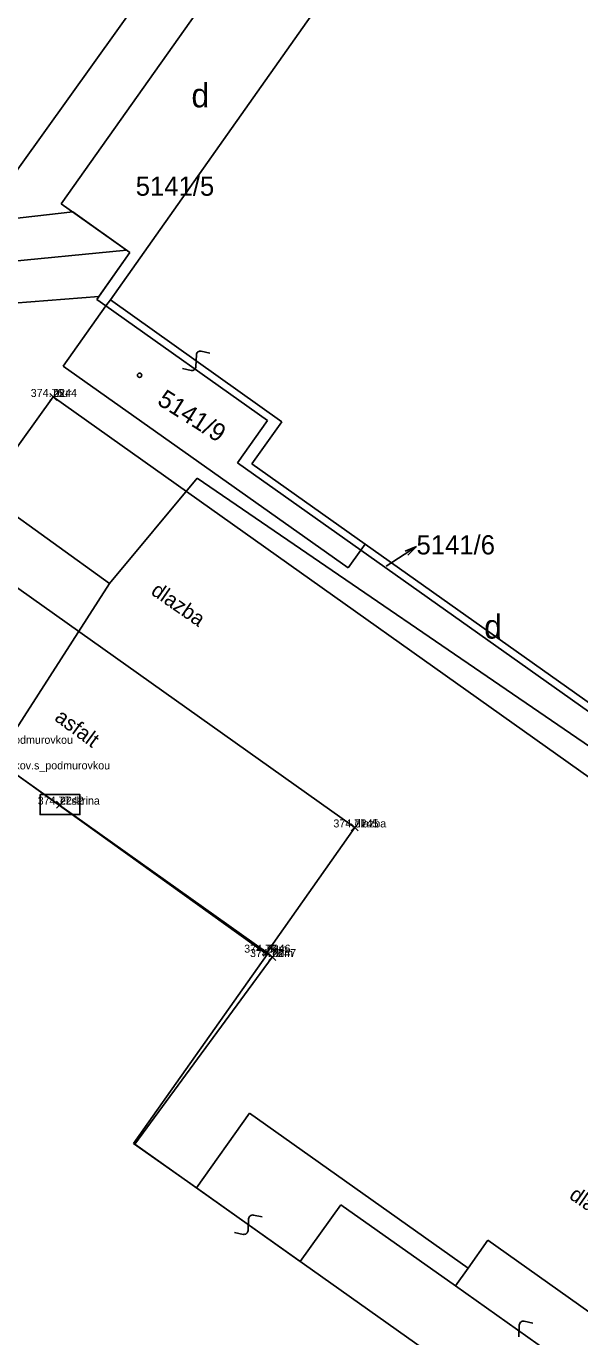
# Model space of a CAD drawing. Extents: x -400488 to -400124, y -1251493 to -1251223.
# Drawn here: x -400338.08 to -400324.23, y -1251319.82 to -1251287.06 of the extents above; entities that cross this region are included whole.
import ezdxf

# ---------------------------------------------------------------- set-up
doc = ezdxf.new("R2010")
doc.units = 0
for name, color, linetype in [('Level 20', 7, 'Continuous'), ('Level 21', 7, 'Continuous'), ('Level 22', 7, 'Continuous'), ('Level 23', 7, 'Continuous'), ('Level 31', 7, 'Continuous'), ('Level 32', 7, 'Continuous'), ('Level 34', 7, 'Continuous'), ('Level 35', 7, 'Continuous'), ('Level 53', 7, 'Continuous'), ('Level 63', 7, 'Continuous')]:
    doc.layers.add(name, color=color, linetype=linetype)

msp = doc.modelspace()

# ---------------------------------------------------------------- linework, layer by layer
at = {"layer": 'Level 20'}
for p, q in [((-400337.488, -1251296.418), (-400337.312, -1251296.242)), ((-400337.312, -1251296.418), (-400337.488, -1251296.242)), ((-400337.318, -1251306.608), (-400337.142, -1251306.432)), ((-400337.142, -1251306.608), (-400337.318, -1251306.432)), ((-400329.948, -1251307.178), (-400329.772, -1251307.002)), ((-400329.772, -1251307.178), (-400329.948, -1251307.002)), ((-400332.148, -1251310.308), (-400331.972, -1251310.132)), ((-400331.972, -1251310.308), (-400332.148, -1251310.132)), ((-400332.008, -1251310.418), (-400331.832, -1251310.242)), ((-400331.832, -1251310.418), (-400332.008, -1251310.242))]:
    msp.add_line(p, q, dxfattribs=at)
at = {"layer": 'Level 31'}
msp.add_lwpolyline([(-400341.165, -1251294.579), (-400341.04, -1251297.05), (-400340.98, -1251298.42), (-400339.65, -1251299.4), (-400340.05, -1251299.86), (-400329.86, -1251307.09), (-400332.06, -1251310.22)], dxfattribs=at)
at = {"layer": 'Level 34'}
for points in [[(-400343.58, -1251312.05), (-400339.12, -1251305.887), (-400338.95, -1251305.64), (-400338.78, -1251305.45), (-400332.06, -1251310.22), (-400331.92, -1251310.33)], [(-400318.045, -1251327.281), (-400335.362, -1251315.009), (-400331.92, -1251310.33)]]:
    msp.add_lwpolyline(points, dxfattribs=at)
at = {"layer": 'Level 35'}
msp.add_lwpolyline([(-400338.97, -1251298.5), (-400337.4, -1251296.33), (-400320.87, -1251308.06), (-400319.57, -1251311.74)], dxfattribs=at)
at = {"layer": 'Level 53'}
msp.add_lwpolyline([(-400337.73, -1251306.27), (-400336.73, -1251306.27), (-400336.73, -1251306.77), (-400337.73, -1251306.77)], close=True, dxfattribs=at)
at = {"layer": 'Level 63'}
for p, q in [((-400333.05, -1251283.33), (-400342.41, -1251296.38)), ((-400342.41, -1251296.38), (-400333.05, -1251283.33)), ((-400328.67, -1251283.57), (-400335.97, -1251293.9)), ((-400335.97, -1251293.9), (-400328.67, -1251283.57)), ((-400332.29, -1251284.57), (-400337.2, -1251291.5)), ((-400337.2, -1251291.5), (-400332.29, -1251284.57)), ((-400339.25, -1251291.97), (-400336.91, -1251291.7)), ((-400337.2, -1251291.5), (-400335.48, -1251292.72)), ((-400335.48, -1251292.72), (-400337.2, -1251291.5)), ((-400336.91, -1251291.7), (-400335.48, -1251292.72)), ((-400340.05, -1251293.1), (-400335.57, -1251292.66)), ((-400335.48, -1251292.72), (-400336.31, -1251293.89)), ((-400336.31, -1251293.89), (-400335.48, -1251292.72)), ((-400335.48, -1251292.72), (-400336.26, -1251293.82)), ((-400336.26, -1251293.82), (-400340.59, -1251294.16)), ((-400336.08, -1251294.05), (-400337.15, -1251295.56)), ((-400337.15, -1251295.56), (-400336.08, -1251294.05)), ((-400336.31, -1251293.89), (-400336.08, -1251294.05)), ((-400336.08, -1251294.05), (-400336.31, -1251293.89)), ((-400335.97, -1251293.9), (-400336.08, -1251294.05)), ((-400336.08, -1251294.05), (-400335.97, -1251293.9)), ((-400336.08, -1251294.05), (-400332.04, -1251296.92)), ((-400332.04, -1251296.92), (-400336.08, -1251294.05)), ((-400331.68, -1251296.95), (-400335.97, -1251293.9)), ((-400333.831, -1251295.572), (-400333.819, -1251295.278)), ((-400333.698, -1251295.184), (-400333.48, -1251295.232)), ((-400337.15, -1251295.56), (-400330.02, -1251300.6)), ((-400330.02, -1251300.6), (-400337.15, -1251295.56)), ((-400334.17, -1251295.618), (-400333.952, -1251295.666)), ((-400342.41, -1251296.38), (-400335.99, -1251300.99)), ((-400335.99, -1251300.99), (-400342.41, -1251296.38)), ((-400332.04, -1251296.92), (-400332.79, -1251297.98)), ((-400332.79, -1251297.98), (-400332.04, -1251296.92)), ((-400332.43, -1251298), (-400331.68, -1251296.95)), ((-400332.79, -1251297.98), (-400329.71, -1251300.16)), ((-400329.71, -1251300.16), (-400332.79, -1251297.98)), ((-400329.6, -1251300.01), (-400332.43, -1251298)), ((-400335.99, -1251300.99), (-400333.8, -1251298.36)), ((-400333.8, -1251298.36), (-400335.99, -1251300.99)), ((-400333.8, -1251298.36), (-400320.99, -1251307.12)), ((-400320.99, -1251307.12), (-400333.8, -1251298.36)), ((-400330.02, -1251300.6), (-400329.71, -1251300.16)), ((-400329.71, -1251300.16), (-400330.02, -1251300.6)), ((-400329.71, -1251300.16), (-400329.6, -1251300.01)), ((-400329.6, -1251300.01), (-400329.71, -1251300.16)), ((-400329.71, -1251300.16), (-400323.81, -1251304.33)), ((-400323.81, -1251304.33), (-400329.71, -1251300.16)), ((-400329.6, -1251300.01), (-400323.7, -1251304.18)), ((-400323.7, -1251304.18), (-400329.6, -1251300.01)), ((-400329.07, -1251300.56), (-400328.316, -1251300.069)), ((-400328.316, -1251300.069), (-400328.6, -1251300.182)), ((-400328.535, -1251300.283), (-400328.316, -1251300.069)), ((-400335.99, -1251300.99), (-400338.69, -1251305.2)), ((-400338.69, -1251305.2), (-400335.99, -1251300.99)), ((-400338.84, -1251305.4), (-400332.05, -1251310.27)), ((-400332.05, -1251310.27), (-400335.39, -1251314.99)), ((-400335.39, -1251314.99), (-400332.05, -1251310.27)), ((-400333.82, -1251316.1), (-400332.49, -1251314.23)), ((-400332.49, -1251314.23), (-400333.82, -1251316.1)), ((-400332.49, -1251314.23), (-400327.02, -1251318.11)), ((-400327.02, -1251318.11), (-400332.49, -1251314.23)), ((-400335.39, -1251314.99), (-400333.82, -1251316.1)), ((-400333.82, -1251316.1), (-400335.39, -1251314.99)), ((-400333.82, -1251316.1), (-400331.22, -1251317.94)), ((-400331.22, -1251317.94), (-400330.21, -1251316.52)), ((-400330.21, -1251316.52), (-400327.34, -1251318.55)), ((-400332.526, -1251317.167), (-400332.514, -1251316.873)), ((-400332.393, -1251316.779), (-400332.175, -1251316.827)), ((-400332.865, -1251317.213), (-400332.647, -1251317.261)), ((-400327.02, -1251318.11), (-400326.53, -1251317.41)), ((-400326.53, -1251317.41), (-400327.02, -1251318.11)), ((-400326.53, -1251317.41), (-400323.36, -1251319.66)), ((-400323.36, -1251319.66), (-400326.53, -1251317.41)), ((-400327.02, -1251318.11), (-400327.34, -1251318.55)), ((-400327.34, -1251318.55), (-400324.16, -1251320.8)), ((-400325.756, -1251319.822), (-400325.744, -1251319.528)), ((-400325.623, -1251319.434), (-400325.405, -1251319.482))]:
    msp.add_line(p, q, dxfattribs=at)
msp.add_circle((-400335.24, -1251295.786), 0.054, dxfattribs=at)
for centre, start, end in [((-400333.719, -1251295.282), 77.7527, 177.7631), ((-400333.931, -1251295.568), 257.753, 357.7631), ((-400332.414, -1251316.877), 77.7527, 177.7631), ((-400332.626, -1251317.163), 257.753, 357.7631), ((-400325.644, -1251319.532), 77.7527, 177.7631)]:
    msp.add_arc(centre, 0.1, start, end, dxfattribs=at)

# ---------------------------------------------------------------- texts
at = {"layer": 'Level 21'}
for s, p in [('2244', (-400337.4, -1251296.33)), ('2242', (-400337.23, -1251306.52)), ('2245', (-400329.86, -1251307.09)), ('2246', (-400332.06, -1251310.22)), ('2247', (-400331.92, -1251310.33))]:
    msp.add_text(s, height=0.2, dxfattribs=at).set_placement(p)
at = {"layer": 'Level 22'}
for s, p in [('mur', (-400337.4, -1251296.33)), ('plot_kov.s_podmurovkou', (-400339.88, -1251305)), ('plot_kov.s_podmurovkou', (-400338.95, -1251305.64)), ('el.skrina', (-400337.23, -1251306.52)), ('dlazba', (-400329.86, -1251307.09)), ('dom', (-400332.06, -1251310.22)), ('dom', (-400331.92, -1251310.33))]:
    msp.add_text(s, height=0.2, dxfattribs=at).set_placement(p)
at = {"layer": 'Level 23'}
for s, p in [('374.76', (-400337.963, -1251296.33)), ('374.77', (-400337.788, -1251306.52)), ('374.71', (-400330.393, -1251307.09)), ('374.76', (-400332.623, -1251310.22)), ('374.78', (-400332.478, -1251310.33))]:
    msp.add_text(s, height=0.2, dxfattribs=at).set_placement(p)
at = {"layer": 'Level 31'}
for p in [(-400334.981, -1251301.244), (-400324.52, -1251316.347)]:
    msp.add_text('dlazba', height=0.375, rotation=325.2178, dxfattribs=at).set_placement(p)
at = {"layer": 'Level 32'}
msp.add_text('asfalt', height=0.375, rotation=323.6458, dxfattribs=at).set_placement((-400337.39, -1251304.4))
at = {"layer": 'Level 63'}
for s, height, p in [('d', 0.6, (-400333.943, -1251289.09)), ('5141/5', 0.48, (-400335.336, -1251291.3)), ('5141/6', 0.48, (-400328.314, -1251300.266)), ('d', 0.6, (-400326.623, -1251302.37))]:
    msp.add_text(s, height=height, dxfattribs=at).set_placement(p)
msp.add_text('5141/9', height=0.45, rotation=327.6517, dxfattribs=at).set_placement((-400334.825, -1251296.498))

doc.saveas('drawing.dxf')
